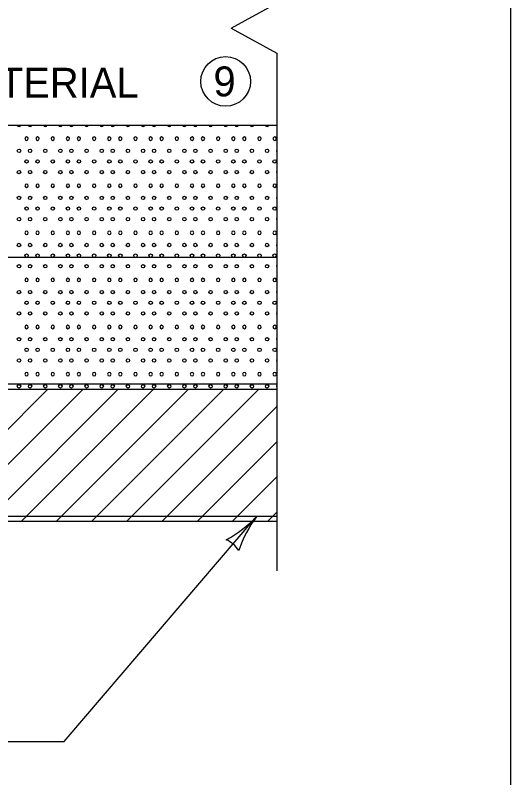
# Model space of a CAD drawing. Extents: x 49991.4 to 50021, y 49987.6 to 50011.4.
# Drawn here: x 50019.942 to 50020.938, y 50005.774 to 50007.305 of the extents above; entities that cross this region are included whole.
import ezdxf

# ---------------------------------------------------------------- set-up
doc = ezdxf.new("R2010")
doc.units = 0
for name, color, linetype in [('Level 1', 7, 'Continuous'), ('Level 2', 7, 'Continuous'), ('Level 3', 7, 'Continuous'), ('Level 6', 7, 'Continuous')]:
    doc.layers.add(name, color=color, linetype=linetype)

msp = doc.modelspace()

# ---------------------------------------------------------------- linework, layer by layer
at = {"layer": 'Level 1'}
for p, q in [((50017.1193, 50007.085), (50020.4675, 50007.085)), ((50017.0193, 50006.8198), (50020.4675, 50006.8198)), ((50020.4675, 50006.5645), (50017.1276, 50006.5644)), ((50017.1193, 50006.5545), (50020.4675, 50006.5545)), ((50019.7422, 50006.2893), (50020.0074, 50006.5545)), ((50019.8129, 50006.2893), (50020.0781, 50006.5545)), ((50019.8836, 50006.2893), (50020.1488, 50006.5545)), ((50019.9543, 50006.2893), (50020.2195, 50006.5545)), ((50020.025, 50006.2893), (50020.2902, 50006.5545)), ((50020.0957, 50006.2893), (50020.3609, 50006.5545)), ((50020.1664, 50006.2893), (50020.4316, 50006.5545)), ((50020.2371, 50006.2893), (50020.4675, 50006.5196)), ((50020.3079, 50006.2893), (50020.4675, 50006.4489)), ((50020.3786, 50006.2893), (50020.4675, 50006.3782)), ((50017.1276, 50006.2993), (50020.4675, 50006.2993)), ((50020.4493, 50006.2893), (50020.4675, 50006.3075)), ((50017.1193, 50006.2893), (50020.4675, 50006.2893))]:
    msp.add_line(p, q, dxfattribs=at)
msp.add_lwpolyline([(50020.9378, 50008.1646), (50009.7374, 50008.1646), (50009.7374, 49999.8856), (50020.9378, 49999.8856)], close=True, dxfattribs=at)
for centre in [(50019.9494, 50007.0332), (50019.9716, 50007.0332), (50020.0021, 50007.0332), (50020.0325, 50007.0332), (50020.0547, 50007.0332), (50020.0852, 50007.0332), (50020.1156, 50007.0332), (50020.1378, 50007.0332), (50020.1683, 50007.0332), (50020.1987, 50007.0332), (50020.2209, 50007.0332), (50020.2514, 50007.0332), (50020.2818, 50007.0332), (50020.304, 50007.0332), (50020.3345, 50007.0332), (50020.3649, 50007.0332), (50020.3871, 50007.0332), (50020.4176, 50007.0332), (50020.448, 50007.0332), (50019.9647, 50007.0118), (50019.9868, 50007.0118), (50020.0173, 50007.0118), (50020.0173, 50007.0118), (50020.0478, 50007.0118), (50020.0699, 50007.0118), (50020.1004, 50007.0118), (50020.1004, 50007.0118), (50020.1309, 50007.0118), (50020.153, 50007.0118), (50020.1835, 50007.0118), (50020.1835, 50007.0118), (50020.214, 50007.0118), (50020.2361, 50007.0118), (50020.2666, 50007.0118), (50020.2666, 50007.0118), (50020.2971, 50007.0118), (50020.3192, 50007.0118), (50020.3497, 50007.0118), (50020.3497, 50007.0118), (50020.3802, 50007.0118), (50020.4023, 50007.0118), (50020.4328, 50007.0118), (50020.4328, 50007.0118), (50020.4633, 50007.0118), (50019.9494, 50006.9905), (50019.9716, 50006.9905), (50020.0021, 50006.9905), (50020.0325, 50006.9905), (50020.0547, 50006.9905), (50020.0852, 50006.9905), (50020.1156, 50006.9905), (50020.1378, 50006.9905), (50020.1683, 50006.9905), (50020.1987, 50006.9905), (50020.2209, 50006.9905), (50020.2514, 50006.9905), (50020.2818, 50006.9905), (50020.304, 50006.9905), (50020.3345, 50006.9905), (50020.3649, 50006.9905), (50020.3871, 50006.9905), (50020.4176, 50006.9905), (50020.448, 50006.9905), (50019.9494, 50006.9386), (50019.9716, 50006.9386), (50020.0021, 50006.9386), (50020.0325, 50006.9386), (50020.0547, 50006.9386), (50020.0852, 50006.9386), (50020.1156, 50006.9386), (50020.1378, 50006.9386), (50020.1683, 50006.9386), (50020.1987, 50006.9386), (50020.2209, 50006.9386), (50020.2514, 50006.9386), (50020.2818, 50006.9386), (50020.304, 50006.9386), (50020.3345, 50006.9386), (50020.3649, 50006.9386), (50020.3871, 50006.9386), (50020.4176, 50006.9386), (50020.448, 50006.9386), (50019.9647, 50006.9172), (50019.9868, 50006.9172), (50020.0173, 50006.9172), (50020.0173, 50006.9172), (50020.0478, 50006.9172), (50020.0699, 50006.9172), (50020.1004, 50006.9172), (50020.1004, 50006.9172), (50020.1309, 50006.9172), (50020.153, 50006.9172), (50020.1835, 50006.9172), (50020.1835, 50006.9172), (50020.214, 50006.9172), (50020.2361, 50006.9172), (50020.2666, 50006.9172), (50020.2666, 50006.9172), (50020.2971, 50006.9172), (50020.3192, 50006.9172), (50020.3497, 50006.9172), (50020.3497, 50006.9172), (50020.3802, 50006.9172), (50020.4023, 50006.9172), (50020.4328, 50006.9172), (50020.4328, 50006.9172), (50020.4633, 50006.9172), (50019.9494, 50006.8959), (50019.9716, 50006.8959), (50020.0021, 50006.8959), (50020.0325, 50006.8959), (50020.0547, 50006.8959), (50020.0852, 50006.8959), (50020.1156, 50006.8959), (50020.1378, 50006.8959), (50020.1683, 50006.8959), (50020.1987, 50006.8959), (50020.2209, 50006.8959), (50020.2514, 50006.8959), (50020.2818, 50006.8959), (50020.304, 50006.8959), (50020.3345, 50006.8959), (50020.3649, 50006.8959), (50020.3871, 50006.8959), (50020.4176, 50006.8959), (50020.448, 50006.8959), (50019.9494, 50006.844), (50019.9716, 50006.844), (50020.0021, 50006.844), (50020.0325, 50006.844), (50020.0547, 50006.844), (50020.0852, 50006.844), (50020.1156, 50006.844), (50020.1378, 50006.844), (50020.1683, 50006.844), (50020.1987, 50006.844), (50020.2209, 50006.844), (50020.2514, 50006.844), (50020.2818, 50006.844), (50020.304, 50006.844), (50020.3345, 50006.844), (50020.3649, 50006.844), (50020.3871, 50006.844), (50020.4176, 50006.844), (50020.448, 50006.844), (50019.9647, 50006.8226), (50019.9868, 50006.8226), (50020.0173, 50006.8226), (50020.0173, 50006.8226), (50020.0478, 50006.8226), (50020.0699, 50006.8226), (50020.1004, 50006.8226), (50020.1004, 50006.8226), (50020.1309, 50006.8226), (50020.153, 50006.8226), (50020.1835, 50006.8226), (50020.1835, 50006.8226), (50020.214, 50006.8226), (50020.2361, 50006.8226), (50020.2666, 50006.8226), (50020.2666, 50006.8226), (50020.2971, 50006.8226), (50020.3192, 50006.8226), (50020.3497, 50006.8226), (50020.3497, 50006.8226), (50020.3802, 50006.8226), (50020.4023, 50006.8226), (50020.4328, 50006.8226), (50020.4328, 50006.8226), (50020.4633, 50006.8226), (50019.9494, 50006.8013), (50019.9716, 50006.8013), (50020.0021, 50006.8013), (50020.0325, 50006.8013), (50020.0547, 50006.8013), (50020.0852, 50006.8013), (50020.1156, 50006.8013), (50020.1378, 50006.8013), (50020.1683, 50006.8013), (50020.1987, 50006.8013), (50020.2209, 50006.8013), (50020.2514, 50006.8013), (50020.2818, 50006.8013), (50020.304, 50006.8013), (50020.3345, 50006.8013), (50020.3649, 50006.8013), (50020.3871, 50006.8013), (50020.4176, 50006.8013), (50020.448, 50006.8013), (50019.9494, 50006.7494), (50019.9716, 50006.7494), (50020.0021, 50006.7494), (50020.0325, 50006.7494), (50020.0547, 50006.7494), (50020.0852, 50006.7494), (50020.1156, 50006.7494), (50020.1378, 50006.7494), (50020.1683, 50006.7494), (50020.1987, 50006.7494), (50020.2209, 50006.7494), (50020.2514, 50006.7494), (50020.2818, 50006.7494), (50020.304, 50006.7494), (50020.3345, 50006.7494), (50020.3649, 50006.7494), (50020.3871, 50006.7494), (50020.4176, 50006.7494), (50020.448, 50006.7494), (50019.9647, 50006.728), (50019.9868, 50006.728), (50020.0173, 50006.728), (50020.0173, 50006.728), (50020.0478, 50006.728), (50020.0699, 50006.728), (50020.1004, 50006.728), (50020.1004, 50006.728), (50020.1309, 50006.728), (50020.153, 50006.728), (50020.1835, 50006.728), (50020.1835, 50006.728), (50020.214, 50006.728), (50020.2361, 50006.728), (50020.2666, 50006.728), (50020.2666, 50006.728), (50020.2971, 50006.728), (50020.3192, 50006.728), (50020.3497, 50006.728), (50020.3497, 50006.728), (50020.3802, 50006.728), (50020.4023, 50006.728), (50020.4328, 50006.728), (50020.4328, 50006.728), (50020.4633, 50006.728), (50019.9494, 50006.7067), (50019.9716, 50006.7067), (50020.0021, 50006.7067), (50020.0325, 50006.7067), (50020.0547, 50006.7067), (50020.0852, 50006.7067), (50020.1156, 50006.7067), (50020.1378, 50006.7067), (50020.1683, 50006.7067), (50020.1987, 50006.7067), (50020.2209, 50006.7067), (50020.2514, 50006.7067), (50020.2818, 50006.7067), (50020.304, 50006.7067), (50020.3345, 50006.7067), (50020.3649, 50006.7067), (50020.3871, 50006.7067), (50020.4176, 50006.7067), (50020.448, 50006.7067), (50019.9494, 50006.6548), (50019.9716, 50006.6548), (50020.0021, 50006.6548), (50020.0325, 50006.6548), (50020.0547, 50006.6548), (50020.0852, 50006.6548), (50020.1156, 50006.6548), (50020.1378, 50006.6548), (50020.1683, 50006.6548), (50020.1987, 50006.6548), (50020.2209, 50006.6548), (50020.2514, 50006.6548), (50020.2818, 50006.6548), (50020.304, 50006.6548), (50020.3345, 50006.6548), (50020.3649, 50006.6548), (50020.3871, 50006.6548), (50020.4176, 50006.6548), (50020.448, 50006.6548), (50019.9647, 50006.6334), (50019.9868, 50006.6334), (50020.0173, 50006.6334), (50020.0173, 50006.6334), (50020.0478, 50006.6334), (50020.0699, 50006.6334), (50020.1004, 50006.6334), (50020.1004, 50006.6334), (50020.1309, 50006.6334), (50020.153, 50006.6334), (50020.1835, 50006.6334), (50020.1835, 50006.6334), (50020.214, 50006.6334), (50020.2361, 50006.6334), (50020.2666, 50006.6334), (50020.2666, 50006.6334), (50020.2971, 50006.6334), (50020.3192, 50006.6334), (50020.3497, 50006.6334), (50020.3497, 50006.6334), (50020.3802, 50006.6334), (50020.4023, 50006.6334), (50020.4328, 50006.6334), (50020.4328, 50006.6334), (50020.4633, 50006.6334), (50019.9494, 50006.6121), (50019.9716, 50006.6121), (50020.0021, 50006.6121), (50020.0325, 50006.6121), (50020.0547, 50006.6121), (50020.0852, 50006.6121), (50020.1156, 50006.6121), (50020.1378, 50006.6121), (50020.1683, 50006.6121), (50020.1987, 50006.6121), (50020.2209, 50006.6121), (50020.2514, 50006.6121), (50020.2818, 50006.6121), (50020.304, 50006.6121), (50020.3345, 50006.6121), (50020.3649, 50006.6121), (50020.3871, 50006.6121), (50020.4176, 50006.6121), (50020.448, 50006.6121), (50019.9494, 50006.5602), (50019.9716, 50006.5602), (50020.0021, 50006.5602), (50020.0325, 50006.5602), (50020.0547, 50006.5602), (50020.0852, 50006.5602), (50020.1156, 50006.5602), (50020.1378, 50006.5602), (50020.1683, 50006.5602), (50020.1987, 50006.5602), (50020.2209, 50006.5602), (50020.2514, 50006.5602), (50020.2818, 50006.5602), (50020.304, 50006.5602), (50020.3345, 50006.5602), (50020.3649, 50006.5602), (50020.3871, 50006.5602), (50020.4176, 50006.5602), (50020.448, 50006.5602)]:
    msp.add_circle(centre, 0.00341, dxfattribs=at)
for centre, start, end in [((50019.9494, 50007.0851), 181.8336, 358.1664), ((50019.9716, 50007.0851), 181.8336, 358.1664), ((50020.0021, 50007.0851), 181.8336, 358.1664), ((50020.0325, 50007.0851), 181.8336, 358.1664), ((50020.0547, 50007.0851), 181.8336, 358.1664), ((50020.0852, 50007.0851), 181.8336, 358.1664), ((50020.1156, 50007.0851), 181.8336, 358.1664), ((50020.1378, 50007.0851), 181.8336, 358.1664), ((50020.1683, 50007.0851), 181.8336, 358.1664), ((50020.1987, 50007.0851), 181.8336, 358.1664), ((50020.2209, 50007.0851), 181.8336, 358.1664), ((50020.2514, 50007.0851), 181.8336, 358.1664), ((50020.2818, 50007.0851), 181.8336, 358.1664), ((50020.304, 50007.0851), 181.8336, 358.1664), ((50020.3345, 50007.0851), 181.8336, 358.1664), ((50020.3649, 50007.0851), 181.8336, 358.1664), ((50020.3871, 50007.0851), 181.8336, 358.1664), ((50020.4176, 50007.0851), 181.8336, 358.1664), ((50020.448, 50007.0851), 181.8336, 358.1664), ((50020.4702, 50007.0851), 181.8336, 217.4029), ((50019.9647, 50007.0577), 0, 180), ((50019.9647, 50007.0576), 180, 0), ((50019.9868, 50007.0577), 0, 180), ((50019.9868, 50007.0576), 180, 0), ((50020.0173, 50007.0577), 0, 180), ((50020.0173, 50007.0576), 180, 0), ((50020.0173, 50007.0576), 180, 0), ((50020.0478, 50007.0577), 0, 180), ((50020.0478, 50007.0576), 180, 0), ((50020.0699, 50007.0577), 0, 180), ((50020.0699, 50007.0576), 180, 0), ((50020.1004, 50007.0577), 0, 180), ((50020.1004, 50007.0576), 180, 0), ((50020.1004, 50007.0576), 180, 0), ((50020.1309, 50007.0577), 0, 180), ((50020.1309, 50007.0576), 180, 0), ((50020.153, 50007.0577), 0, 180), ((50020.153, 50007.0576), 180, 0), ((50020.1835, 50007.0577), 0, 180), ((50020.1835, 50007.0576), 180, 0), ((50020.1835, 50007.0576), 180, 0), ((50020.214, 50007.0577), 0, 180), ((50020.214, 50007.0576), 180, 0), ((50020.2361, 50007.0577), 0, 180), ((50020.2361, 50007.0576), 180, 0), ((50020.2666, 50007.0577), 0, 180), ((50020.2666, 50007.0576), 180, 0), ((50020.2666, 50007.0576), 180, 0), ((50020.2971, 50007.0577), 0, 180), ((50020.2971, 50007.0576), 180, 0), ((50020.3192, 50007.0577), 0, 180), ((50020.3192, 50007.0576), 180, 0), ((50020.3497, 50007.0577), 0, 180), ((50020.3497, 50007.0576), 180, 0), ((50020.3497, 50007.0576), 180, 0), ((50020.3802, 50007.0577), 0, 180), ((50020.3802, 50007.0576), 180, 0), ((50020.4023, 50007.0577), 0, 180), ((50020.4023, 50007.0576), 180, 0), ((50020.4328, 50007.0577), 0, 180), ((50020.4328, 50007.0576), 180, 0), ((50020.4328, 50007.0576), 180, 0), ((50020.4633, 50007.0577), 0, 180), ((50020.4633, 50007.0576), 180, 0), ((50020.4702, 50007.0332), 142.5971, 217.4029), ((50020.4702, 50006.9905), 142.5971, 217.4029), ((50019.9647, 50006.9631), 0, 180), ((50019.9647, 50006.963), 180, 0), ((50019.9868, 50006.9631), 0, 180), ((50019.9868, 50006.963), 180, 0), ((50020.0173, 50006.9631), 0, 180), ((50020.0173, 50006.963), 180, 0), ((50020.0173, 50006.963), 180, 0), ((50020.0478, 50006.9631), 0, 180), ((50020.0478, 50006.963), 180, 0), ((50020.0699, 50006.9631), 0, 180), ((50020.0699, 50006.963), 180, 0), ((50020.1004, 50006.9631), 0, 180), ((50020.1004, 50006.963), 180, 0), ((50020.1004, 50006.963), 180, 0), ((50020.1309, 50006.9631), 0, 180), ((50020.1309, 50006.963), 180, 0), ((50020.153, 50006.9631), 0, 180), ((50020.153, 50006.963), 180, 0), ((50020.1835, 50006.9631), 0, 180), ((50020.1835, 50006.963), 180, 0), ((50020.1835, 50006.963), 180, 0), ((50020.214, 50006.9631), 0, 180), ((50020.214, 50006.963), 180, 0), ((50020.2361, 50006.9631), 0, 180), ((50020.2361, 50006.963), 180, 0), ((50020.2666, 50006.9631), 0, 180), ((50020.2666, 50006.963), 180, 0), ((50020.2666, 50006.963), 180, 0), ((50020.2971, 50006.9631), 0, 180), ((50020.2971, 50006.963), 180, 0), ((50020.3192, 50006.9631), 0, 180), ((50020.3192, 50006.963), 180, 0), ((50020.3497, 50006.9631), 0, 180), ((50020.3497, 50006.963), 180, 0), ((50020.3497, 50006.963), 180, 0), ((50020.3802, 50006.9631), 0, 180), ((50020.3802, 50006.963), 180, 0), ((50020.4023, 50006.9631), 0, 180), ((50020.4023, 50006.963), 180, 0), ((50020.4328, 50006.9631), 0, 180), ((50020.4328, 50006.963), 180, 0), ((50020.4328, 50006.963), 180, 0), ((50020.4633, 50006.9631), 0, 180), ((50020.4633, 50006.963), 180, 0), ((50020.4702, 50006.9386), 142.5971, 217.4029), ((50020.4702, 50006.8959), 142.5971, 217.4029), ((50019.9647, 50006.8685), 0, 180), ((50019.9647, 50006.8684), 180, 0), ((50019.9868, 50006.8685), 0, 180), ((50019.9868, 50006.8684), 180, 0), ((50020.0173, 50006.8685), 0, 180), ((50020.0173, 50006.8684), 180, 0), ((50020.0173, 50006.8684), 180, 0), ((50020.0478, 50006.8685), 0, 180), ((50020.0478, 50006.8684), 180, 0), ((50020.0699, 50006.8685), 0, 180), ((50020.0699, 50006.8684), 180, 0), ((50020.1004, 50006.8685), 0, 180), ((50020.1004, 50006.8684), 180, 0), ((50020.1004, 50006.8684), 180, 0), ((50020.1309, 50006.8685), 0, 180), ((50020.1309, 50006.8684), 180, 0), ((50020.153, 50006.8685), 0, 180), ((50020.153, 50006.8684), 180, 0), ((50020.1835, 50006.8685), 0, 180), ((50020.1835, 50006.8684), 180, 0), ((50020.1835, 50006.8684), 180, 0), ((50020.214, 50006.8685), 0, 180), ((50020.214, 50006.8684), 180, 0), ((50020.2361, 50006.8685), 0, 180), ((50020.2361, 50006.8684), 180, 0), ((50020.2666, 50006.8685), 0, 180), ((50020.2666, 50006.8684), 180, 0), ((50020.2666, 50006.8684), 180, 0), ((50020.2971, 50006.8685), 0, 180), ((50020.2971, 50006.8684), 180, 0), ((50020.3192, 50006.8685), 0, 180), ((50020.3192, 50006.8684), 180, 0), ((50020.3497, 50006.8685), 0, 180), ((50020.3497, 50006.8684), 180, 0), ((50020.3497, 50006.8684), 180, 0), ((50020.3802, 50006.8685), 0, 180), ((50020.3802, 50006.8684), 180, 0), ((50020.4023, 50006.8685), 0, 180), ((50020.4023, 50006.8684), 180, 0), ((50020.4328, 50006.8685), 0, 180), ((50020.4328, 50006.8684), 180, 0), ((50020.4328, 50006.8684), 180, 0), ((50020.4633, 50006.8685), 0, 180), ((50020.4633, 50006.8684), 180, 0), ((50020.4702, 50006.844), 142.5971, 217.4029), ((50020.4702, 50006.8013), 142.5971, 217.4029), ((50019.9647, 50006.7739), 0, 180), ((50019.9647, 50006.7738), 180, 0), ((50019.9868, 50006.7739), 0, 180), ((50019.9868, 50006.7738), 180, 0), ((50020.0173, 50006.7739), 0, 180), ((50020.0173, 50006.7738), 180, 0), ((50020.0173, 50006.7738), 180, 0), ((50020.0478, 50006.7739), 0, 180), ((50020.0478, 50006.7738), 180, 0), ((50020.0699, 50006.7739), 0, 180), ((50020.0699, 50006.7738), 180, 0), ((50020.1004, 50006.7739), 0, 180), ((50020.1004, 50006.7738), 180, 0), ((50020.1004, 50006.7738), 180, 0), ((50020.1309, 50006.7739), 0, 180), ((50020.1309, 50006.7738), 180, 0), ((50020.153, 50006.7739), 0, 180), ((50020.153, 50006.7738), 180, 0), ((50020.1835, 50006.7739), 0, 180), ((50020.1835, 50006.7738), 180, 0), ((50020.1835, 50006.7738), 180, 0), ((50020.214, 50006.7739), 0, 180), ((50020.214, 50006.7738), 180, 0), ((50020.2361, 50006.7739), 0, 180), ((50020.2361, 50006.7738), 180, 0), ((50020.2666, 50006.7739), 0, 180), ((50020.2666, 50006.7738), 180, 0), ((50020.2666, 50006.7738), 180, 0), ((50020.2971, 50006.7739), 0, 180), ((50020.2971, 50006.7738), 180, 0), ((50020.3192, 50006.7739), 0, 180), ((50020.3192, 50006.7738), 180, 0), ((50020.3497, 50006.7739), 0, 180), ((50020.3497, 50006.7738), 180, 0), ((50020.3497, 50006.7738), 180, 0), ((50020.3802, 50006.7739), 0, 180), ((50020.3802, 50006.7738), 180, 0), ((50020.4023, 50006.7739), 0, 180), ((50020.4023, 50006.7738), 180, 0), ((50020.4328, 50006.7739), 0, 180), ((50020.4328, 50006.7738), 180, 0), ((50020.4328, 50006.7738), 180, 0), ((50020.4633, 50006.7739), 0, 180), ((50020.4633, 50006.7738), 180, 0), ((50020.4702, 50006.7494), 142.5971, 217.4029), ((50020.4702, 50006.7067), 142.5971, 217.4029), ((50019.9647, 50006.6793), 0, 180), ((50019.9647, 50006.6792), 180, 0), ((50019.9868, 50006.6793), 0, 180), ((50019.9868, 50006.6792), 180, 0), ((50020.0173, 50006.6793), 0, 180), ((50020.0173, 50006.6792), 180, 0), ((50020.0173, 50006.6792), 180, 0), ((50020.0478, 50006.6793), 0, 180), ((50020.0478, 50006.6792), 180, 0), ((50020.0699, 50006.6793), 0, 180), ((50020.0699, 50006.6792), 180, 0), ((50020.1004, 50006.6793), 0, 180), ((50020.1004, 50006.6792), 180, 0), ((50020.1004, 50006.6792), 180, 0), ((50020.1309, 50006.6793), 0, 180), ((50020.1309, 50006.6792), 180, 0), ((50020.153, 50006.6793), 0, 180), ((50020.153, 50006.6792), 180, 0), ((50020.1835, 50006.6793), 0, 180), ((50020.1835, 50006.6792), 180, 0), ((50020.1835, 50006.6792), 180, 0), ((50020.214, 50006.6793), 0, 180), ((50020.214, 50006.6792), 180, 0), ((50020.2361, 50006.6793), 0, 180), ((50020.2361, 50006.6792), 180, 0), ((50020.2666, 50006.6793), 0, 180), ((50020.2666, 50006.6792), 180, 0), ((50020.2666, 50006.6792), 180, 0), ((50020.2971, 50006.6793), 0, 180), ((50020.2971, 50006.6792), 180, 0), ((50020.3192, 50006.6793), 0, 180), ((50020.3192, 50006.6792), 180, 0), ((50020.3497, 50006.6793), 0, 180), ((50020.3497, 50006.6792), 180, 0), ((50020.3497, 50006.6792), 180, 0), ((50020.3802, 50006.6793), 0, 180), ((50020.3802, 50006.6792), 180, 0), ((50020.4023, 50006.6793), 0, 180), ((50020.4023, 50006.6792), 180, 0), ((50020.4328, 50006.6793), 0, 180), ((50020.4328, 50006.6792), 180, 0), ((50020.4328, 50006.6792), 180, 0), ((50020.4633, 50006.6793), 0, 180), ((50020.4633, 50006.6792), 180, 0), ((50020.4702, 50006.6548), 142.5971, 217.4029), ((50020.4702, 50006.6121), 142.5971, 217.4029), ((50019.9647, 50006.5847), 0, 180), ((50019.9868, 50006.5847), 0, 180), ((50020.0173, 50006.5847), 0, 180), ((50020.0478, 50006.5847), 0, 180), ((50020.0699, 50006.5847), 0, 180), ((50020.1004, 50006.5847), 0, 180), ((50020.1309, 50006.5847), 0, 180), ((50020.153, 50006.5847), 0, 180), ((50020.1835, 50006.5847), 0, 180), ((50020.214, 50006.5847), 0, 180), ((50020.2361, 50006.5847), 0, 180), ((50020.2666, 50006.5847), 0, 180), ((50020.2971, 50006.5847), 0, 180), ((50020.3192, 50006.5847), 0, 180), ((50020.3497, 50006.5847), 0, 180), ((50020.3802, 50006.5847), 0, 180), ((50020.4023, 50006.5847), 0, 180), ((50020.4328, 50006.5847), 0, 180), ((50020.4633, 50006.5847), 0, 180), ((50019.9647, 50006.5846), 180, 0), ((50019.9868, 50006.5846), 180, 0), ((50020.0173, 50006.5846), 180, 0), ((50020.0173, 50006.5846), 180, 0), ((50020.0478, 50006.5846), 180, 0), ((50020.0699, 50006.5846), 180, 0), ((50020.1004, 50006.5846), 180, 0), ((50020.1004, 50006.5846), 180, 0), ((50020.1309, 50006.5846), 180, 0), ((50020.153, 50006.5846), 180, 0), ((50020.1835, 50006.5846), 180, 0), ((50020.1835, 50006.5846), 180, 0), ((50020.214, 50006.5846), 180, 0), ((50020.2361, 50006.5846), 180, 0), ((50020.2666, 50006.5846), 180, 0), ((50020.2666, 50006.5846), 180, 0), ((50020.2971, 50006.5846), 180, 0), ((50020.3192, 50006.5846), 180, 0), ((50020.3497, 50006.5846), 180, 0), ((50020.3497, 50006.5846), 180, 0), ((50020.3802, 50006.5846), 180, 0), ((50020.4023, 50006.5846), 180, 0), ((50020.4328, 50006.5846), 180, 0), ((50020.4328, 50006.5846), 180, 0), ((50020.4633, 50006.5846), 180, 0), ((50020.4702, 50006.5602), 142.5971, 217.4029)]:
    msp.add_arc(centre, 0.00341, start, end, dxfattribs=at)
at = {"layer": 'Level 2'}
msp.add_circle((50020.3647, 50007.1726), 0.05, dxfattribs=at)
at = {"layer": 'Level 3'}
for p, q in [((50020.0403, 50005.847), (50020.4275, 50006.2993)), ((50019.607, 50005.847), (50020.0403, 50005.847))]:
    msp.add_line(p, q, dxfattribs=at)
for centre, radius, start, end in [((50020.2636, 50006.4496), 0.2223, 297.2969, 317.4804), ((50020.6128, 50006.158), 0.233, 142.6682, 161.918), ((50020.3448, 50006.2013), 0.0548, 31.9797, 67.7021)]:
    msp.add_arc(centre, radius, start, end, dxfattribs=at)
at = {"layer": 'Level 6'}
for p, q in [((50020.3761, 50007.2796), (50020.4675, 50007.3296)), ((50020.3761, 50007.2796), (50020.4675, 50007.2296)), ((50020.4675, 50007.2296), (50020.4675, 50006.1893))]:
    msp.add_line(p, q, dxfattribs=at)

# ---------------------------------------------------------------- texts
at = {"layer": 'Level 2'}
for s, p in [('BEDDING MATERIAL', (50019.4007, 50007.1399)), ('9', (50020.3402, 50007.1426))]:
    msp.add_text(s, height=0.06, dxfattribs=at).set_placement(p)

doc.saveas('drawing.dxf')
